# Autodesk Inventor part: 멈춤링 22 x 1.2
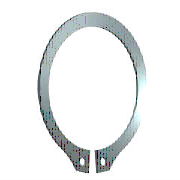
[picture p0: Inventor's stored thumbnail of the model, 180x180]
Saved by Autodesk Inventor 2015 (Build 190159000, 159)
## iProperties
IsCustomPart: 0
Created: 2009-02
Part Number: 멈춤링 22 x 1.2
Material: Steel, Mild
Description: 리테이닝 링(C형)
Document SubType Name: Modeling
Standard: KS B 1336
Designer: SeoGD™
Standards Organization: KS
Language: ko-KR
Size Designation: 22 x 1.2
Categories: <MemberInstance><Categories><Category DisplayName="샤프트 부품" InternalName="7f7aeb1f-a693-4053-b835-cee3144e0d98" Mnemonic="SHFT"><Category DisplayName="써클립" Inter
Density: 7.86 g/cm^3
Appearance: Metal-Steel
Mass: 1.8286 g
Surface Area: 5.91219 cm^2
Volume: 0.232646 cm^3
Author: SeoGD™
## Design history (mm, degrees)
sketch "스케치1"
  geometry: L1 (-6, 0)-(6, 0) reference; L2 (0, 20.189)-(0, -80.536) reference; L3 (-48.09, 0)-(48.09, 0) reference; L4 (-0.5, -21.488)-(-0.5, -25.588); L5 (-0.5, -6.54)-(-0.5, -13.29); L6 (-2.795, 2.7)-(3.672, 2.7); L7 (0.5, -6.54)-(0.5, -13.29); L8 (0.5, -21.488)-(0.5, -25.588); C1 r 1 at (-2, -23.437); C2 r 1 at (2, -23.437); A1 r 10.5 centre (0, -11) between (0.5, -21.488) and (-0.5, -21.488); A2 r 13.025 centre (0, -10.325) between (5.149, -22.289) and (-5.149, -22.289); A3 r 14.597 centre (0, -11) between (-2.318, -25.411) and (-0.5, -25.588); A4 r 2 centre (-2, -23.437) between (-3.97, -23.781) and (-2.318, -25.411); A5 r 2 centre (-5.94, -24.126) between (-3.97, -23.781) and (-5.149, -22.289); A6 r 2 centre (5.94, -24.126) between (5.149, -22.289) and (3.97, -23.781); A7 r 2 centre (2, -23.437) between (2.318, -25.411) and (3.97, -23.781); A8 r 14.597 centre (0, -11) between (0.5, -25.588) and (2.318, -25.411)
  constraints: 16 point on circle, 12 end point, 10 centre point, 9 symmetric about line, 5 point on line, 4 tangent, 3 coincident, 2 horizontal, 1 perpendicular, 1 vertical, 5 other
  dimensions: "d0" = 21 diameter of A1 (= ND); "d1" = 4.1 distance of L4.end L4.start (= SRB2); "d6" = 0.5 distance between parallel lines of L2 L5 (= 0.25 x SD5); "d7" = 2.7 distance between parallel lines of L6 L3 (= SRB1); "d8" = 0.675 distance of A1.centre A2.centre (= 0.25 x SRB1); "d9" = 2 radius of A4 (= SD5); "d10" = 2 radius of A5 (= SD5); "d11" = 1.5 distance from line of L4 A4.centre (= 0.75 x SD5); "d12" = 2 diameter of C1 (= SD5); "d13" = 2 diameter of C2 (= SD5); "d14" = 11 distance from line of A1.centre L1 (= 0.5 x WD)
extrude "본체" new body sketch "스케치1" distance "d2" = 1.2 (= SD); taper "d3" = 0 deg
workaxis "Work Axis1"
workplane "Work Plane1"
body "Solid1"
other parameters: "WD" = 22 (= WDMIN) [user parameter; used in 1 equation term], "SD" = 1.2 [user parameter; used in 1 equation term], "SRB1" = 2.7 [user parameter; used in 2 equation terms], "ND" = 21 [user parameter; used in 1 equation term], "SRB2" = 4.1 [user parameter; used in 1 equation term], "SD5" = 2 [user parameter; used in 6 equation terms], "d15" = 0, "d16" = 0, "d17" = 0, "d41" = 0, "d42" = 0, "WDMIN" = 22 [user parameter; used in 1 equation term], "SD3" = 20.5 [user parameter], "WDMAX" = 24 [user parameter]
